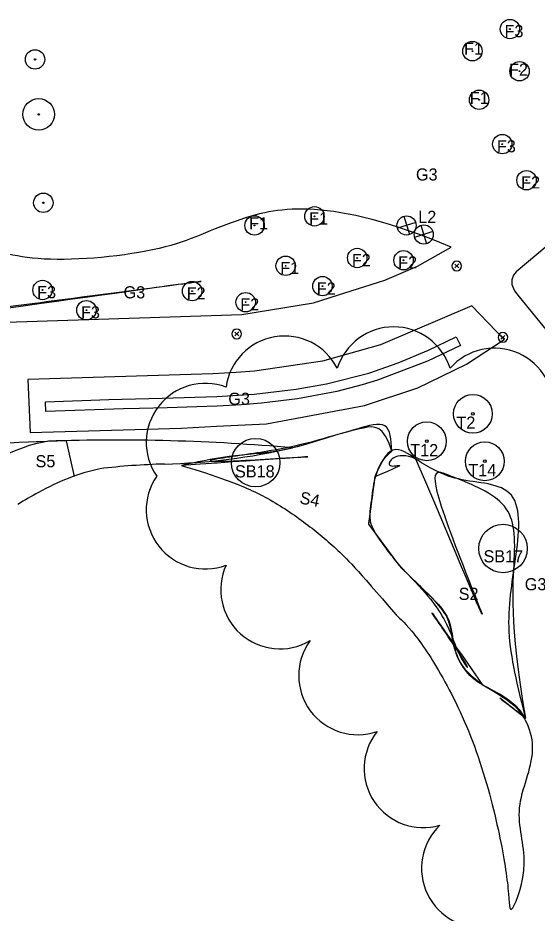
# Model space of a CAD drawing. Extents: x 0 to 512122, y 0 to 6212554.
# Drawn here: x 511645.3 to 511698.8, y 6211506.3 to 6211598.5 of the extents above; entities that cross this region are included whole.
import ezdxf

# ---------------------------------------------------------------- set-up
doc = ezdxf.new("R2010")
doc.units = 0
for name, color, linetype in [('_lights', 7, 'Continuous'), ('_Låge L2', 7, 'Continuous'), ('_ny fruit trees', 7, 'Continuous'), ('_Paths', 7, 'Continuous'), ('_S2_skovjorbær', 7, 'Continuous'), ('_S4_Løvstikke', 7, 'Continuous'), ('_S5_spansk kørvel', 7, 'Continuous'), ('_solitaire tree_ K3', 7, 'Continuous'), ('Clouds', 7, 'Continuous'), ('L40 jord udlagt muld og grøft', 7, 'Continuous'), ('MatrikelnummerMaster', 7, 'Continuous'), ('Skel', 7, 'Continuous'), ('TV_U_AFM_Symbl_Gul', 7, 'Continuous'), ('TV_U_LYS_Mastenummer', 7, 'Continuous'), ('TV_U_LYS_Nyx330-Trafiksti-x2', 7, 'Continuous')]:
    doc.layers.add(name, color=color, linetype=linetype)

# ---------------------------------------------------------------- blocks, each defined once
blk = doc.blocks.new('SOLITAIRE TREES')
at = {"layer": 'Skel'}
for radius in [2, 0.141]:
    blk.add_circle((0, 0), radius, dxfattribs=at)

msp = doc.modelspace()

# ---------------------------------------------------------------- linework, layer by layer
at = {"layer": '_lights'}
for p, q in [((511690.349, 6211573.153), (511690.743, 6211572.759)), ((511690.747, 6211573.157), (511690.353, 6211572.763)), ((511667.66, 6211566.152), (511668.054, 6211565.758)), ((511668.058, 6211566.156), (511667.664, 6211565.762)), ((511695.101, 6211565.797), (511695.495, 6211565.403)), ((511695.499, 6211565.801), (511695.105, 6211565.407))]:
    msp.add_line(p, q, dxfattribs=at)
for centre, start, end in [((511690.546, 6211572.956), 315.56363, 315), ((511690.546, 6211572.956), 315, 315.56363), ((511667.857, 6211565.955), 315.56363, 315), ((511667.857, 6211565.955), 315, 315.56363), ((511695.298, 6211565.6), 315.56363, 315), ((511695.298, 6211565.6), 315, 315.56363)]:
    msp.add_arc(centre, 0.5, start, end, dxfattribs=at)
at = {"layer": '_Låge L2'}
for p, q in [((511685.074, 6211578.072), (511685.66, 6211576.183)), ((511686.311, 6211577.421), (511684.423, 6211576.834)), ((511686.843, 6211577.14), (511687.43, 6211575.251)), ((511688.081, 6211576.489), (511686.192, 6211575.902))]:
    msp.add_line(p, q, dxfattribs=at)
for centre in [(511685.367, 6211577.127), (511687.137, 6211576.195)]:
    msp.add_circle(centre, 0.989, dxfattribs=at)
at = {"layer": '_ny fruit trees'}
for centre, radius in [((511696.027, 6211597.359), 1), ((511696.027, 6211597.359), 0.0426), ((511692.159, 6211595.082), 1), ((511692.159, 6211595.082), 0.0426), ((511697.013, 6211593.013), 1), ((511697.013, 6211593.013), 0.0426), ((511692.853, 6211590.073), 1), ((511647.428, 6211588.567), 1.622), ((511692.853, 6211590.073), 0.0426), ((511647.428, 6211588.567), 0.0691), ((511695.238, 6211585.508), 1), ((511695.238, 6211585.508), 0.0426), ((511697.736, 6211581.783), 1), ((511697.736, 6211581.783), 0.0426), ((511675.87, 6211578.064), 1), ((511669.686, 6211577.124), 1), ((511675.87, 6211578.064), 0.0426), ((511669.686, 6211577.124), 0.0426), ((511680.277, 6211573.777), 1), ((511672.901, 6211572.972), 1), ((511680.277, 6211573.777), 0.0426), ((511685.054, 6211573.542), 1), ((511672.901, 6211572.972), 0.0426), ((511685.054, 6211573.542), 0.0426), ((511647.827, 6211570.476), 1), ((511663.247, 6211570.364), 1), ((511676.692, 6211570.877), 1), ((511647.827, 6211570.476), 0.0426), ((511663.247, 6211570.364), 0.0426), ((511668.773, 6211569.218), 1), ((511676.692, 6211570.877), 0.0426), ((511652.351, 6211568.4), 1), ((511668.773, 6211569.218), 0.0426), ((511652.351, 6211568.4), 0.0426)]:
    msp.add_circle(centre, radius, dxfattribs=at)
at = {"layer": '_Paths'}
msp.add_arc((511888.3, 6211739.773), 228.678, 210.53527, 218.83127, dxfattribs=at)
at = {"layer": '_S2_skovjorbær'}
for p in [(511681.437, 6211546.348), (511681.437, 6211546.348), (511684.574, 6211542.116)]:
    msp.add_line(p, (511684.574, 6211542.116), dxfattribs=at)
for points, degree in [([(511686.337, 6211553.064), (511685.61, 6211553.573), (511683.743, 6211554.882), (511682.714, 6211552.614), (511682.086, 6211551.229)], 3), ([(511686.337, 6211553.064), (511684.284, 6211554.05), (511682.086, 6211551.229), (511686.337, 6211553.064), (511682.086, 6211551.229)], 3), ([(511697.658, 6211526.362), (511695.967, 6211536.372), (511696.737, 6211543.604), (511696.341, 6211548.941), (511689.327, 6211551.421), (511686.337, 6211553.064), (511697.658, 6211526.362), (511686.337, 6211553.064)], 3), ([(511697.658, 6211526.362), (511696.816, 6211529.744), (511695.372, 6211535.548), (511696.694, 6211542.615), (511697.527, 6211550.723), (511690.24, 6211550.481), (511687.27, 6211552.446), (511686.337, 6211553.064)], 3), ([(511682.086, 6211551.229), (511681.437, 6211546.348), (511682.086, 6211551.229), (511681.437, 6211546.348)], 3), ([(511682.086, 6211551.229), (511681.869, 6211549.602), (511681.653, 6211547.975), (511681.437, 6211546.348)], 2), ([(511684.574, 6211542.116), (511687.151, 6211539.594), (511689.667, 6211536.483), (511690.691, 6211532.451), (511693.18, 6211529.825), (511684.574, 6211542.116), (511693.18, 6211529.825)], 3), ([(511684.574, 6211542.116), (511685.419, 6211541.279), (511687.202, 6211539.512), (511690.249, 6211536.712), (511690.053, 6211532.306), (511692.187, 6211530.613), (511693.18, 6211529.825)], 3), ([(511693.18, 6211529.825), (511695.557, 6211528.458), (511696.831, 6211527.417), (511697.649, 6211526.371), (511697.658, 6211526.362), (511693.18, 6211529.825), (511697.658, 6211526.362)], 3), ([(511693.18, 6211529.825), (511693.981, 6211529.391), (511695.263, 6211528.698), (511696.845, 6211527.572), (511697.339, 6211526.681), (511697.655, 6211526.365), (511697.658, 6211526.362)], 3)]:
    msp.add_open_spline(points, degree=degree, dxfattribs=at)
at = {"layer": '_S4_Løvstikke'}
for points in [[(511683.849, 6211553.891), (511683.782, 6211555.09), (511683.666, 6211557.154), (511680.299, 6211556.165), (511677.18, 6211555.275), (511672.289, 6211553.691), (511667.073, 6211553.461), (511663.575, 6211552.709), (511662.152, 6211552.403)], [(511683.849, 6211553.891), (511683.037, 6211556.6), (511681.008, 6211556.375), (511677.511, 6211555.35), (511672.736, 6211554.038), (511666.431, 6211553.222), (511662.152, 6211552.403), (511683.849, 6211553.891), (511662.152, 6211552.403)], [(511685.975, 6211540.729), (511684.542, 6211542.115), (511683.028, 6211544.227), (511681.34, 6211546.437), (511681.801, 6211548.85), (511682.075, 6211551.434), (511682.847, 6211553.05), (511683.849, 6211553.891)], [(511685.975, 6211540.729), (511684.542, 6211542.115), (511683.028, 6211544.227), (511681.34, 6211546.437), (511681.801, 6211548.85), (511682.075, 6211551.434), (511682.847, 6211553.05), (511683.849, 6211553.891)], [(511662.152, 6211552.403), (511663.203, 6211552.084), (511666.454, 6211551.097), (511670.86, 6211549.275), (511674.852, 6211546.61), (511678.114, 6211543.899), (511680.167, 6211541.843), (511684.284, 6211537.007)], [(511662.152, 6211552.403), (511663.203, 6211552.084), (511666.454, 6211551.097), (511670.86, 6211549.275), (511674.852, 6211546.61), (511678.114, 6211543.899), (511680.167, 6211541.843), (511684.284, 6211537.007)], [(511684.284, 6211537.007), (511684.428, 6211536.886), (511685.741, 6211535.765), (511688.738, 6211531.476), (511692.6, 6211523.753), (511695.052, 6211514.395), (511695.991, 6211508.321), (511695.913, 6211505.289), (511698.241, 6211511.568), (511696.129, 6211517.014), (511699.378, 6211523.188), (511696.552, 6211528.633), (511691.805, 6211529.955), (511689.906, 6211534.034), (511690.083, 6211536.875), (511687.618, 6211539.149), (511685.975, 6211540.729)], [(511684.284, 6211537.007), (511684.428, 6211536.886), (511685.741, 6211535.765), (511688.738, 6211531.476), (511692.6, 6211523.753), (511695.052, 6211514.395), (511695.991, 6211508.321), (511695.913, 6211505.289), (511698.241, 6211511.568), (511696.129, 6211517.014), (511699.378, 6211523.188), (511696.552, 6211528.633), (511691.805, 6211529.955), (511689.906, 6211534.034), (511690.083, 6211536.875), (511687.618, 6211539.149), (511685.975, 6211540.729)]]:
    msp.add_open_spline(points, degree=3, dxfattribs=at)
at = {"layer": '_S5_spansk kørvel'}
for centre, radius, start, end in [((511650.867, 6211540.016), 15.09, 99.23851, 140.37499), ((511650.867, 6211540.016), 15.09, 99.23851, 140.37499), ((511655.269, 6211344.838), 210.183, 84.99847, 91.86057), ((511655.269, 6211344.838), 210.183, 84.99847, 91.86057), ((511658.715, 6211618.679), 66.153, 271.44934, 282.99733), ((511658.715, 6211618.679), 66.153, 271.44934, 282.99733), ((511658.662, 6211529.94), 22.665, 102.57784, 119.78754), ((511658.662, 6211529.94), 22.665, 102.57784, 119.78754), ((511662.164, 6211482.346), 70.224, 91.44934, 96.90102), ((511662.164, 6211482.346), 70.224, 91.44934, 96.90102), ((511666.214, 6211514.311), 39.999, 118.0529, 121.55181), ((511666.214, 6211514.311), 39.999, 118.0529, 121.55181)]:
    msp.add_arc(centre, radius, start, end, dxfattribs=at)
at = {"layer": '_solitaire tree_ K3'}
for centre, radius in [((511647.052, 6211594.234), 1), ((511647.052, 6211594.234), 0.0703), ((511647.909, 6211579.462), 1), ((511647.909, 6211579.462), 0.0703)]:
    msp.add_circle(centre, radius, dxfattribs=at)
at = {"layer": 'Clouds'}
for centre, radius, start, end in [((511684.037, 6211560.581), 6.1, 17.5, 162.5), ((511672.788, 6211559.639), 6.1, 27.07893, 172.07893), ((511694.432, 6211558.386), 6.099, 353.63977, 138.63977), ((511664.618, 6211554.765), 6.098, 69.57416, 214.57416), ((511664.623, 6211547.846), 6.101, 145.46517, 290.46517), ((511672.308, 6211539.608), 6.098, 155.57148, 300.57148), ((511680.345, 6211530.768), 6.103, 143.97552, 288.97552), ((511687.089, 6211521.188), 6.096, 141.3266, 286.3266), ((511693.012, 6211510.918), 6.103, 133.60483, 278.60483)]:
    msp.add_arc(centre, radius, start, end, dxfattribs=at)
at = {"layer": 'L40 jord udlagt muld og grøft'}
msp.add_lwpolyline([(511699.849, 6211575.03), (511696.652, 6211572.362), (511696.388, 6211572.021), (511696.214, 6211571.529), (511696.212, 6211571.043), (511696.484, 6211570.394), (511696.979, 6211569.786), (511709.631, 6211554.305)], dxfattribs=at)
for points in [[(511695.426, 6211565.365), (511692.097, 6211568.86), (511682.67, 6211564.837), (511676.704, 6211563.149), (511669.698, 6211562.114), (511667.794, 6211561.978), (511665.401, 6211561.842), (511646.318, 6211561.267), (511646.552, 6211555.805), (511662.141, 6211556.23), (511665.777, 6211556.448), (511670.921, 6211556.697), (511681.031, 6211558.591), (511686.543, 6211560.385), (511691.536, 6211562.843)], [(511690.48, 6211565.653), (511690.943, 6211564.767), (511687.542, 6211563.142), (511682.375, 6211561.195), (511680.798, 6211560.717), (511678.159, 6211560.036), (511674.129, 6211559.262), (511670.422, 6211558.816), (511668.329, 6211558.652), (511665.831, 6211558.519), (511663.746, 6211558.441), (511660.684, 6211558.356), (511657.813, 6211558.279), (511656.192, 6211558.234), (511648.161, 6211557.973), (511648.118, 6211558.972), (511654.668, 6211559.191), (511660.158, 6211559.342), (511665.788, 6211559.518), (511669.642, 6211559.752), (511673.978, 6211560.25), (511677.095, 6211560.825), (511681.471, 6211561.917), (511684.502, 6211562.988), (511687.627, 6211564.27)]]:
    msp.add_lwpolyline(points, close=True, dxfattribs=at)
at = {"layer": 'MatrikelnummerMaster'}
msp.add_lwpolyline([(511625.811, 6211566.048), (511638.798, 6211567), (511668.377, 6211567.95), (511675.766, 6211569.152), (511678.237, 6211569.935), (511683.129, 6211571.5), (511686.511, 6211572.95), (511689.962, 6211574.907)], dxfattribs=at)
msp.add_open_spline([(511689.962, 6211574.907), (511677.385, 6211580.148), (511666.763, 6211577.81), (511661.475, 6211574.432), (511646.361, 6211573.006), (511641.114, 6211575.532), (511631.762, 6211574.259), (511626.338, 6211567.388), (511625.811, 6211566.048), (511689.962, 6211574.907), (511625.811, 6211566.048)], degree=3, dxfattribs=at)
at = {"layer": 'TV_U_LYS_Mastenummer'}
for centre in [(511669.805, 6211552.696), (511695.319, 6211543.849)]:
    msp.add_circle(centre, 2.5, dxfattribs=at)
at = {"layer": 'TV_U_LYS_Nyx330-Trafiksti-x2'}
for points in [[(511650.265, 6211554.946), (511650.074, 6211554.939), (511649.341, 6211554.913), (511648.353, 6211554.876), (511647.367, 6211554.838), (511647.161, 6211554.829), (511646.382, 6211554.797), (511646.371, 6211554.797), (511645.398, 6211554.755), (511644.415, 6211554.71)], [(511650.265, 6211554.946), (511651.103, 6211551.264)]]:
    msp.add_lwpolyline(points, dxfattribs=at)

# ---------------------------------------------------------------- block references
at = {"layer": 'Skel'}
for p in [(511692.209, 6211557.726), (511687.453, 6211554.895), (511693.438, 6211552.834)]:
    msp.add_blockref('SOLITAIRE TREES', p, dxfattribs=at)

# ---------------------------------------------------------------- texts
at = {"layer": 'TV_U_AFM_Symbl_Gul'}
for s, p in [('F3', (511695.473, 6211596.511)), ('F1', (511691.293, 6211594.713)), ('F2', (511695.938, 6211592.55)), ('F1', (511691.884, 6211589.624)), ('F3', (511694.684, 6211584.659)), ('G3', (511686.336, 6211581.753)), ('F2', (511697.182, 6211580.935)), ('F1', (511675.316, 6211577.216)), ('L2', (511686.574, 6211577.392)), ('F1', (511669.132, 6211576.722)), ('F2', (511679.723, 6211572.929)), ('F2', (511684.5, 6211572.694)), ('F1', (511672.347, 6211572.123)), ('F2', (511676.109, 6211570.005)), ('F3', (511647.272, 6211569.628)), ('G3', (511656.181, 6211569.616)), ('F2', (511662.693, 6211569.515)), ('F2', (511668.219, 6211568.37)), ('F3', (511651.796, 6211567.552)), ('G3', (511666.984, 6211558.652)), ('T2', (511690.507, 6211556.191)), ('T12', (511685.75, 6211553.36)), ('S5', (511647.101, 6211552.216)), ('SB18', (511667.673, 6211551.175)), ('T14', (511691.736, 6211551.299)), ('SB17', (511693.301, 6211542.422)), ('G3', (511697.556, 6211539.545)), ('S2', (511690.745, 6211538.551))]:
    msp.add_text(s, height=1.25, dxfattribs=at).set_placement(p)
msp.add_text('S4', height=1.25, rotation=348.84094, dxfattribs=at).set_placement((511674.265, 6211548.509))

doc.saveas('drawing.dxf')
